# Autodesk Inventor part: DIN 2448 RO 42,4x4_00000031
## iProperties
Created: 2006-02
Part Number: DIN 2448 RO 42,4x4_00000031
Material: Default
Document SubType Name: Modeling
Designer: FranzK
Stock Number: DIN 2448 RO 42,4x4
Mass: 1645.49 g
Surface Area: 8237.11 cm^2
Volume: 1645.49 cm^3
Density: 1 g/cm^3
G_L: 3410.000 mm
G_W: 42.400 mm
G_H: 42.400 mm
AFG_Item: 42.4 x 4
CSToolsMass: 2.0
CSToolsVolume: 1645491.0
CSToolsArea: 8237.0
Author: FranzK
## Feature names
1. AFG_Detailed_DIN 2448 RO 42,4x4_00000031 [Extrusion]
2. AFG_Simplified_DIN 2448 RO 42,4x4_00000031 [Extrusion]
